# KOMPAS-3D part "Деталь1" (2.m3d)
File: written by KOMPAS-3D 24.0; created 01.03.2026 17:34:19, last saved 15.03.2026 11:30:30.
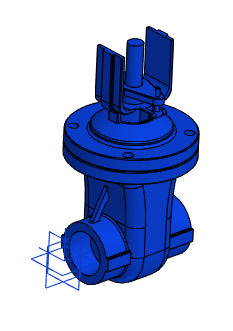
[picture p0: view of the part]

Document properties: Автор: R2D2; Полное имя файла: E:\Работа\Зайцев\GVWR2626M-2W-F-S Задвижка клиновая с выдвижным штоком DN.ru Ду50-300 Ру16\DN50\исходные материалы\2.m3d

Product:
- Body: Твердое тело1  | qty 1
    Масса: 12.23036
- Part/product: Деталь1
    Масса: 12.23036
    additional columns: Типовые

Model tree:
1. Твердое тело1  (labels: Твердое тело1)
2. Эскиз:1
3. Элемент выдавливания:1
     Расстояние 1 = 500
